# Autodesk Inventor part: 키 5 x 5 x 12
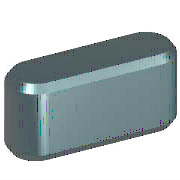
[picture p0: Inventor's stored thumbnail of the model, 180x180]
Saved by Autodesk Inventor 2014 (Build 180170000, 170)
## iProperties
Created: 2012-02
Part Number: 키 5 x 5 x 12
Material: 강철, 연강
Description: 키 및 해당 키홈
Document SubType Name: Modeling
Standard: KS B 1311
Designer: mduedu
Standards Organization: KS
Language: ko-KR
Size Designation: 5 x 5 x 12
Categories: <MemberInstance><Categories><Category DisplayName="샤프트 부품" InternalName="7f7aeb1f-a693-4053-b835-cee3144e0d98" Mnemonic="SHFT"><Category DisplayName="키" Interna
Density: 1 g/cm^3
Appearance: Yellow
IsCustomPart: 1
Author: mduedu
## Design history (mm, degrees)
sketch "스케치1"
  geometry: L1 (2.5, 2.5)-(9.5, 2.5); L2 (9.5, -2.5)-(2.5, -2.5); L3 (0, 9.4)-(0, -7.4) reference; L4 (-5, 0)-(30, 0) reference; L5 (12, 0)-(12, 7); A1 r 2.5 centre (2.5, 0) between (2.5, 2.5) and (2.5, -2.5); A2 r 2.5 centre (9.5, 0) between (9.5, -2.5) and (9.5, 2.5)
  constraints: 6 end point, 5 point on circle, 4 tangent, 3 point on line, 2 centre point, 1 horizontal, 1 parallel, 1 perpendicular
  dimensions: "d0" = 2.5 radius of A1 (= 0.5 x PB); "d13" = 2.5 radius of A2 (= 0.5 x PB); "d14" = 12 distance between parallel lines of L5 L3 (= NLG)
extrude "본체1" new body sketch "스케치1" taper "d3" = 0 deg; stored distance "d4" = 10
workplane "Work Plane3"
body "Solid1"
workplane "Work Plane1"
workplane "Work Plane2"
chamfer "모따기1" distance "d8" = 0.4 (= PHH); stored, may be unused: second distance "d9" = 0.4 (= PHH), angle "d15" = 45 deg
other parameters: "d1" = -3 (= -PNT), "d2" = 2 (= PH - PNT), "NLG" = 12 [user parameter; used in 3 equation terms], "PB" = 5 [user parameter; used in 2 equation terms], "PNT" = 3 [user parameter; used in 2 equation terms], "PH" = 5 [user parameter; used in 1 equation term], "PHH" = 0.4 [user parameter; used in 2 equation terms], "d10" = 0, "d16" = 0, "d17" = 0, "d18" = 0, "WDMIN" = 12 [user parameter], "PLB2" = 12 (= NLG) [user parameter], "WDMAX" = 17 [user parameter], "PLB1" = 12 (= NLG) [user parameter], "RR" = 0.16 [user parameter], "PUEB" = 2.3 [user parameter]
